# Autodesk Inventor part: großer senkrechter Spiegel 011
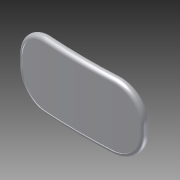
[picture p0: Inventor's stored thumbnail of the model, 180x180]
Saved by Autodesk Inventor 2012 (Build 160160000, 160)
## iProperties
Created: 2012-09
Part Number: großer senkrechter Spiegel 011
Material: Default
Document SubType Name: Modeling
Designer: Hans-Jürgen
Density: 1 g/cm^3
Author: Hans-Jürgen
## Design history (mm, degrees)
sketch "Skizze1"
  geometry: L1 (0, 1.003)-(0.497, 0.948); L2 (-0.497, 0.054)-(-0.497, 1.061); L3 (17.203, -0.055)-(17.203, 0.951); A1 r 79.072 centre (8.838, 78.573) between (-0.497, 0.054) and (17.203, -0.055); A2 r 78.072 centre (8.838, 78.573) between (-0.497, 1.061) and (17.203, 0.951); 1 further point
  constraints: 6 end point, 6 point on circle, 2 centre point, 1 parallel, 1 vertical
  dimensions: "d3" = 0.5 distance of point (0, 0) L2.start; "d5" = 1 radial gap between concentric circles of A2 A1; "d25" = 17.7 horizontal distance of L3.start L2.start
extrude "Extrusion1" new body sketch "Skizze1" stored distance "d6" = 9.3; taper "d7" = 0 deg
fillet "Rundung4" dims "d26" = 4
feature "Wandstärke4" dims "d39" = 0.6
feature "Wandstärke5" dims "d40" = 0.5
fillet "Rundung11" dims "d41" = 0.4
workplane "Arbeitsebene7"
sketch "Skizze5"
  geometry: L1 (0.65, 17.097)-(-0.65, 17.097) reference; L2 (4.05, 3.995)-(4.05, 13.696) reference; L3 (-0.65, 0.597)-(0.65, 0.597) reference; L4 (-4.05, 13.696)-(-4.05, 3.995) reference; 1 further point
  constraints: 4 other
extrude "Extrusion5" join sketch "Skizze5" stored distance "d42" = 10; taper "d43" = 0 deg
fillet "Rundung12" dims "d44" = 0.4
fillet "Rundung13" dims "d45" = 0.5
fillet "Rundung14" dims "d46" = 0.5
sketch "Skizze7"
  geometry: L1 (3.508, 1.036)-(13.208, 0.976) reference; L2 (3.508, 1.036)-(8.358, 1.006); L3 (8.358, 1.006)-(8.383, 5.006); L4 (7.431, 2.515)-(6.858, 1.015); L5 (9.303, 2.503)-(9.858, 0.997); L6 (6.858, 1.015)-(9.858, 0.997); A1 r 1 centre (8.365, 2.158) between (9.303, 2.503) and (7.431, 2.515); 1 further point
  constraints: 10 end point, 4 point on line, 2 point on circle, 2 tangent, 1 centre point, 1 collinear, 1 perpendicular, 1 symmetric about line
  dimensions: "d47" = 4.85 distance of L1.start L2.end; "d48" = 4 distance of L2.end L3.end; "d49" = 1.5 distance from line of L4.end L3; "d50" = 1 radius of A1
extrude "Extrusion6" join sketch "Skizze7" stored distance "d51" = 2; taper "d52" = 0 deg
workplane "Arbeitsebene8"
node "Volumenkörper1"
node "Projizierte Kontur4"
other parameters: "d53" = 90 deg
